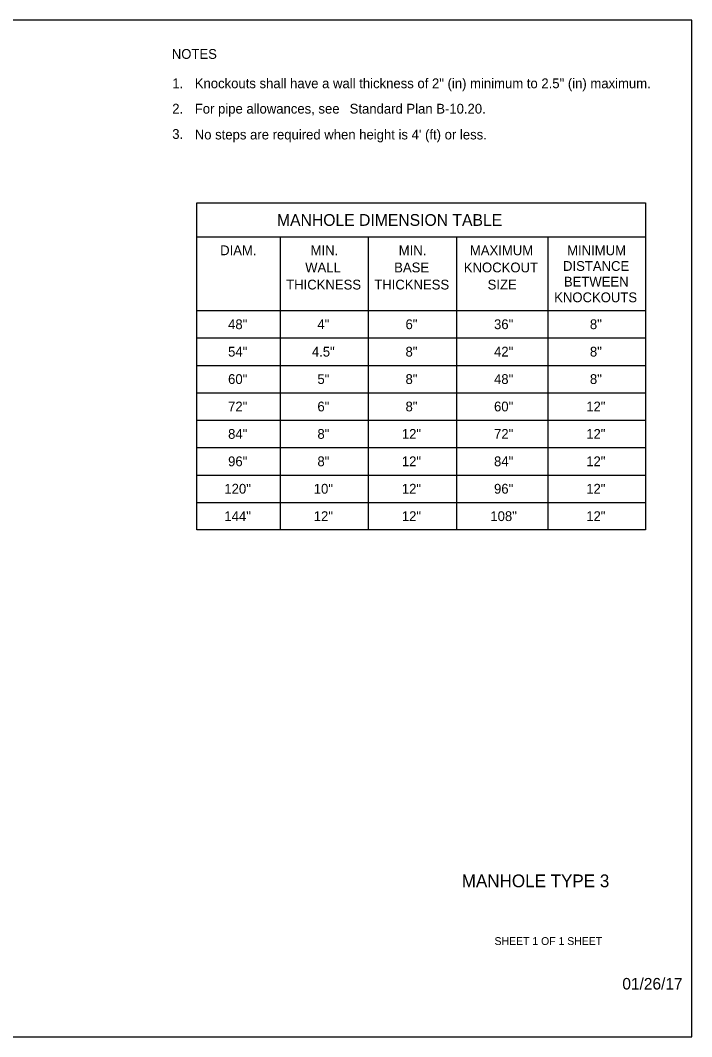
# Model space of a CAD drawing. Extents: x 99862 to 103151, y 100000 to 102076.
# Drawn here: x 101779 to 103151, y 100000 to 102076 of the extents above; entities that cross this region are included whole.
import ezdxf

# ---------------------------------------------------------------- set-up
doc = ezdxf.new("R2010")
doc.units = 0
for name, color, linetype in [('Level 1', 7, 'Continuous'), ('Level 15', 7, 'Continuous'), ('Level 19', 7, 'Continuous'), ('Level 20', 7, 'Continuous'), ('Level 40', 7, 'Continuous'), ('Level 60', 7, 'Continuous'), ('Level 62', 7, 'Continuous')]:
    doc.layers.add(name, color=color, linetype=linetype)

msp = doc.modelspace()

# ---------------------------------------------------------------- linework, layer by layer
at = {"layer": 'Level 1'}
msp.add_lwpolyline([(99862, 99999.5), (103151, 99999.5), (103151, 102075.5), (99862, 102075.5)], close=True, dxfattribs=at)
at = {"layer": 'Level 19'}
for p, q in [((102310.2, 101632.7), (102310.2, 101034.7)), ((102490.2, 101632.7), (102490.2, 101034.7)), ((102670.2, 101632.7), (102670.2, 101034.7)), ((102856.9, 101632.7), (102856.9, 101034.7))]:
    msp.add_line(p, q, dxfattribs=at)
at = {"layer": 'Level 40'}
for p, q in [((103056.9, 101632.7), (102140.2, 101632.7)), ((102140.2, 101482.7), (103056.9, 101482.7)), ((102140.2, 101426.7), (103056.9, 101426.7)), ((102140.2, 101370.7), (103056.9, 101370.7)), ((102140.2, 101314.7), (103056.9, 101314.7)), ((102140.2, 101258.7), (103056.9, 101258.7)), ((102140.2, 101202.7), (103056.9, 101202.7)), ((102140.2, 101146.7), (103056.9, 101146.7)), ((102140.2, 101090.7), (103056.9, 101090.7))]:
    msp.add_line(p, q, dxfattribs=at)
msp.add_lwpolyline([(102140.2, 101702.7), (103056.9, 101702.7), (103056.9, 101034.7), (102140.2, 101034.7)], close=True, dxfattribs=at)
at = {"layer": 'Level 60'}
msp.add_line((103151, 102075.5), (103151, 102075.5), dxfattribs=at)

# ---------------------------------------------------------------- texts
at = {"layer": 'Level 15'}
msp.add_text('01/26/17', height=23.62, dxfattribs=at).set_placement((103009.4, 100095.8))
at = {"layer": 'Level 19'}
msp.add_text('MANHOLE DIMENSION TABLE', height=24, dxfattribs=at).set_placement((102303.8, 101655.7))
at = {"layer": 'Level 20'}
for s, p in [('NOTES', (102088.9, 101996.8)), ('1.', (102089.8, 101936.8)), ('Knockouts shall have a wall thickness of 2" (in) minimum to 2.5" (in) maximum.', (102135.8, 101936.8)), ('2.', (102089.8, 101885)), ('For pipe allowances, see', (102135.8, 101885)), (' Standard Plan B-10.20.', (102444.8, 101885)), ('3.', (102089.8, 101833.3)), ("No steps are required when height is 4' (ft) or less.", (102135.8, 101832.2)), ('DIAM.', (102187.7, 101595.7)), ('MIN.', (102372.5, 101595.7)), ('MIN.', (102552.5, 101595.7)), ('MAXIMUM', (102697.9, 101595.7)), ('MINIMUM ', (102896.5, 101595.7)), ('WALL', (102361.4, 101560.7)), ('BASE', (102543.2, 101560.7)), ('KNOCKOUT', (102685.5, 101560.7)), ('DISTANCE', (102888.2, 101563.7)), ('THICKNESS', (102322.5, 101525.7)), ('THICKNESS', (102502.5, 101525.7)), ('SIZE', (102734.1, 101525.7)), ('BETWEEN', (102889.9, 101531.7)), ('KNOCKOUTS', (102870.1, 101499.7)), ('48"', (102203.9, 101444.7)), ('4"', (102386.4, 101444.7)), ('6"', (102566.4, 101444.7)), ('36"', (102747.2, 101444.7)), ('8"', (102943.1, 101444.7)), ('54"', (102203.9, 101388.7)), ('4.5"', (102375.1, 101388.7)), ('8"', (102566.4, 101388.7)), ('42"', (102747.2, 101388.7)), ('8"', (102943.1, 101388.7)), ('60"', (102203.9, 101332.7)), ('5"', (102386.4, 101332.7)), ('8"', (102566.4, 101332.7)), ('48"', (102747.2, 101332.7)), ('8"', (102943.1, 101332.7)), ('72"', (102203.9, 101276.7)), ('6"', (102386.4, 101276.7)), ('8"', (102566.4, 101276.7)), ('60"', (102747.2, 101276.7)), ('12"', (102935.6, 101276.7)), ('84"', (102203.9, 101220.7)), ('8"', (102386.4, 101220.7)), ('12"', (102558.9, 101220.7)), ('72"', (102747.2, 101220.7)), ('12"', (102935.6, 101220.7)), ('96"', (102203.9, 101164.7)), ('8"', (102386.4, 101164.7)), ('12"', (102558.9, 101164.7)), ('84"', (102747.2, 101164.7)), ('12"', (102935.6, 101164.7)), ('120"', (102196.3, 101108.7)), ('10"', (102378.9, 101108.7)), ('12"', (102558.9, 101108.7)), ('96"', (102747.2, 101108.7)), ('12"', (102935.6, 101108.7)), ('144"', (102196.3, 101052.7)), ('12"', (102378.9, 101052.7)), ('12"', (102558.9, 101052.7)), ('108"', (102739.7, 101052.7)), ('12"', (102935.6, 101052.7))]:
    msp.add_text(s, height=20, dxfattribs=at).set_placement(p)
at = {"layer": 'Level 62'}
for s, height, p in [('MANHOLE TYPE 3', 26, (102681.3, 100304.8)), ('SHEET 1 OF 1 SHEET', 16, (102748.2, 100186.8)), ('SHEET 1 OF 1 SHEET', 16, (102748.2, 100186.8))]:
    msp.add_text(s, height=height, dxfattribs=at).set_placement(p)

doc.saveas('drawing.dxf')
